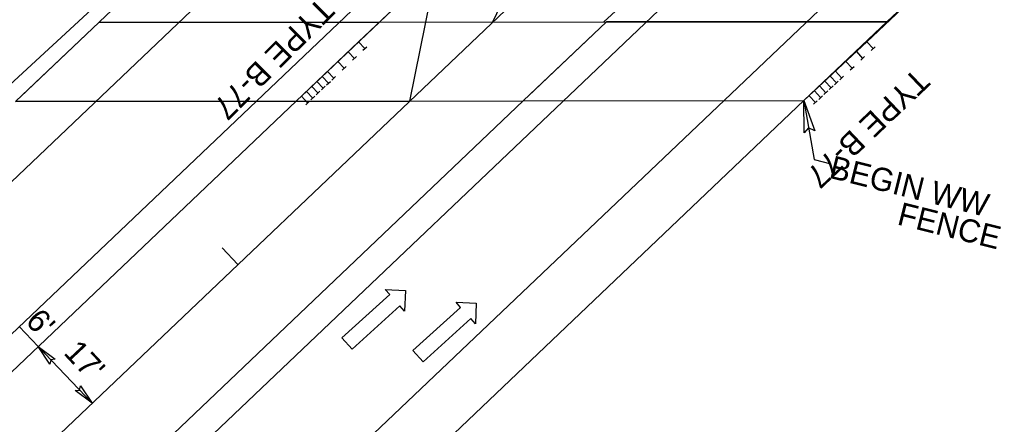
# Model space of a CAD drawing. Extents: x 2389694 to 2405615, y 546931 to 573532.
# Drawn here: x 2397828.9 to 2398045.4, y 559465.7 to 559553.6 of the extents above; entities that cross this region are included whole.
import ezdxf

# ---------------------------------------------------------------- set-up
doc = ezdxf.new("R2010")
doc.units = 0
for name, color, linetype in [('Old_Level_11', 7, 'Continuous'), ('Prop Approach Slab', 7, 'Continuous'), ('Prop Approach Slab Hatching', 7, 'Continuous'), ('Prop Conc Barrier Precast Reinforced Single Face', 7, 'Continuous'), ('Prop Dimension', 7, 'Continuous'), ('Prop Dimension Text', 7, 'Continuous'), ('Prop DSN Text', 7, 'Continuous'), ('Prop EOT', 7, 'Continuous'), ('Prop Guardrail', 7, 'Continuous'), ('Prop Horizontal Alignment', 7, 'Continuous'), ('Prop Horizontal Alignment Tick Small', 7, 'Continuous'), ('Prop Lane Arrow Through CELL', 7, 'Continuous'), ('Prop Lane Lines', 7, 'Continuous'), ('Prop SAU III Approach CELL', 7, 'Continuous')]:
    doc.layers.add(name, color=color, linetype=linetype)

# ---------------------------------------------------------------- blocks, each defined once
blk = doc.blocks.new('TERM')
at = {"layer": 'Old_Level_11'}
blk.add_lwpolyline([(-0.01375, 0.00225), (0, 0), (-0.01375, -0.0025), (-0.012, 0)], close=True, dxfattribs=at)

msp = doc.modelspace()

# ---------------------------------------------------------------- linework, layer by layer
at = {"layer": 'Prop Approach Slab'}
for p, q in [((2397829.03, 559536.85), (2397846.1, 559553.08)), ((2397890.06, 559536.92), (2397907.09, 559553.11)), ((2397939.47, 559536.98), (2397956.52, 559553.19)), ((2398000.5, 559537.05), (2398017.53, 559553.24)), ((2397725.49, 559380.46), (2397888.97, 559535.89)), ((2397774.89, 559380.52), (2397938.38, 559535.95)), ((2397827.94, 559535.82), (2397888.97, 559535.89)), ((2397835.92, 559380.59), (2397999.41, 559536.02)), ((2397938.38, 559535.95), (2397999.41, 559536.02))]:
    msp.add_line(p, q, dxfattribs=at)
at = {"layer": 'Prop Approach Slab Hatching'}
for points in [[(2397907.09, 559553.11), (2397888.97, 559535.89), (2397827.94, 559535.82), (2397846.1, 559553.08)], [(2397999.41, 559536.02), (2398017.53, 559553.24), (2397956.52, 559553.19), (2397938.38, 559535.95)]]:
    msp.add_lwpolyline(points, close=True, dxfattribs=at)
at = {"layer": 'Prop Conc Barrier Precast Reinforced Single Face'}
msp.add_line((2397824.8, 559537.74), (2397872.55, 559581.72), dxfattribs=at)
at = {"layer": 'Prop Dimension'}
for p, q in [((2397931.78, 559553.13), (2398012.75, 559726.19)), ((2397913.68, 559535.92), (2397937.64, 559652.66)), ((2397846.1, 559553.08), (2398017.53, 559553.18)), ((2397827.94, 559535.82), (2397913.68, 559535.92)), ((2397888.97, 559535.89), (2397938.38, 559535.95)), ((2397832.89, 559482.57), (2397828.76, 559486.92)), ((2397844.6, 559470.25), (2397832.89, 559482.57))]:
    msp.add_line(p, q, dxfattribs=at)
for points in [[(2397835.43, 559478.77), (2397832.89, 559482.57), (2397836.59, 559479.84), (2397835.61, 559479.71)], [(2397842.06, 559474.04), (2397844.6, 559470.25), (2397840.91, 559472.98), (2397841.88, 559473.11)]]:
    msp.add_lwpolyline(points, close=True, dxfattribs=at)
at = {"layer": 'Prop DSN Text'}
for p, q in [((2397999.41, 559536.02), (2398001.67, 559523.2)), ((2398001.67, 559523.2), (2398005.28, 559522.3))]:
    msp.add_line(p, q, dxfattribs=at)
at = {"layer": 'Prop EOT'}
for p, q in [((2397075.71, 558804.1), (2398839.56, 560481.03)), ((2397092.24, 558786.7), (2398856.1, 560463.63)), ((2397732.72, 559332.14), (2398887.8, 560430.29)), ((2397749.26, 559314.75), (2398904.33, 560412.9)), ((2397955.93, 559553.19), (2398045.01, 559634.57)), ((2397874.17, 559579.77), (2397846.1, 559553.08)), ((2397907.09, 559553.11), (2397920.68, 559566.03)), ((2398031.24, 559566.03), (2398017.53, 559553.24))]:
    msp.add_line(p, q, dxfattribs=at)
at = {"layer": 'Prop Guardrail'}
for p, q in [((2398013.12, 559548.8), (2398032.74, 559567.4)), ((2397902.56, 559548.81), (2397920.68, 559566.03))]:
    msp.add_line(p, q, dxfattribs=at)
at = {"layer": 'Prop Horizontal Alignment'}
msp.add_line((2396449.76, 558144.15), (2398871.95, 560446.96), dxfattribs=at)
at = {"layer": 'Prop Horizontal Alignment Tick Small'}
msp.add_line((2397876.32, 559500.4), (2397872.87, 559504.02), dxfattribs=at)
at = {"layer": 'Prop Lane Arrow Through CELL'}
for p, q in [((2397909.35, 559493.86), (2397908.34, 559494.97)), ((2397908.34, 559494.97), (2397912.76, 559494.78)), ((2397898.95, 559484.48), (2397909.35, 559493.86)), ((2397912.76, 559494.78), (2397912.56, 559490.29)), ((2397911.56, 559491.41), (2397901.16, 559482.03)), ((2397912.56, 559490.29), (2397911.56, 559491.41)), ((2397914.37, 559481.72), (2397924.76, 559491.09)), ((2397924.76, 559491.09), (2397923.76, 559492.21)), ((2397923.76, 559492.21), (2397928.17, 559492.02)), ((2397928.17, 559492.02), (2397927.98, 559487.53)), ((2397926.97, 559488.64), (2397916.58, 559479.27)), ((2397927.98, 559487.53), (2397926.97, 559488.64)), ((2397901.16, 559482.03), (2397898.95, 559484.48)), ((2397916.58, 559479.27), (2397914.37, 559481.72))]:
    msp.add_line(p, q, dxfattribs=at)
at = {"layer": 'Prop Lane Lines'}
msp.add_line((2397075.71, 558804.1), (2398839.56, 560481.03), dxfattribs=at)
at = {"layer": 'Prop SAU III Approach CELL'}
for p, q in [((2397888.97, 559535.89), (2397902.56, 559548.81)), ((2397902.56, 559548.81), (2397903.94, 559547.36)), ((2397903.52, 559546.96), (2397904.36, 559547.75)), ((2397999.41, 559536.02), (2398013.12, 559548.8)), ((2398013.12, 559548.8), (2398014.49, 559547.34)), ((2398014.07, 559546.95), (2398014.91, 559547.73)), ((2397900.3, 559546.65), (2397901.68, 559545.21)), ((2397901.26, 559544.81), (2397902.09, 559545.6)), ((2398010.84, 559546.67), (2398012.2, 559545.21)), ((2398011.78, 559544.82), (2398012.62, 559545.6)), ((2397898.03, 559544.5), (2397899.41, 559543.05)), ((2397899, 559542.66), (2397899.83, 559543.45)), ((2398008.55, 559544.54), (2398009.92, 559543.08)), ((2398009.5, 559542.69), (2398010.33, 559543.47)), ((2397894.64, 559541.27), (2397896.01, 559539.82)), ((2397895.77, 559542.35), (2397897.15, 559540.9)), ((2397896.73, 559540.5), (2397897.56, 559541.29)), ((2398005.12, 559541.34), (2398006.49, 559539.88)), ((2398006.27, 559542.41), (2398007.63, 559540.95)), ((2398007.21, 559540.56), (2398008.05, 559541.34)), ((2397892.37, 559539.12), (2397893.75, 559537.67)), ((2397893.5, 559540.2), (2397894.88, 559538.75)), ((2397894.47, 559538.35), (2397895.3, 559539.14)), ((2397895.6, 559539.43), (2397896.43, 559540.22)), ((2398002.84, 559539.21), (2398004.2, 559537.75)), ((2398003.98, 559540.28), (2398005.35, 559538.82)), ((2398004.93, 559538.43), (2398005.76, 559539.21)), ((2398006.07, 559539.49), (2398006.91, 559540.27)), ((2397890.11, 559536.97), (2397891.48, 559535.52)), ((2397891.24, 559538.04), (2397892.62, 559536.59)), ((2397892.2, 559536.2), (2397893.03, 559536.99)), ((2397893.33, 559537.27), (2397894.16, 559538.06)), ((2398000.55, 559537.08), (2398001.92, 559535.62)), ((2398001.7, 559538.15), (2398003.06, 559536.69)), ((2398002.64, 559536.3), (2398003.48, 559537.08)), ((2398003.78, 559537.36), (2398004.62, 559538.14)), ((2397891.07, 559535.12), (2397891.9, 559535.91)), ((2398001.5, 559535.23), (2398002.34, 559536.01))]:
    msp.add_line(p, q, dxfattribs=at)

# ---------------------------------------------------------------- block references
at = {"layer": 'Prop DSN Text', "xscale": 500, "yscale": 499.99999999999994, "rotation": 99.99077333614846}
msp.add_blockref('TERM', (2397999.41, 559536.02), dxfattribs=at)

# ---------------------------------------------------------------- texts
at = {"layer": 'Prop Dimension Text'}
for s, rotation, p in [('TYPE B-77', 225.0612, (2397894.15, 559558.7)), ('TYPE B-77', 223.5465, (2398023.75, 559543.31)), ("6'", 313.1053, (2397829.89, 559487.89)), ("17'", 313.1053, (2397838.2, 559481.07))]:
    msp.add_text(s, height=5, rotation=rotation, dxfattribs=at).set_placement(p)
at = {"layer": 'Prop DSN Text'}
for s, p in [('BEGIN WW ', (2398004.66, 559519.29)), ('FENCE', (2398019.5, 559509.15))]:
    msp.add_text(s, height=5, rotation=346, dxfattribs=at).set_placement(p)

doc.saveas('drawing.dxf')
